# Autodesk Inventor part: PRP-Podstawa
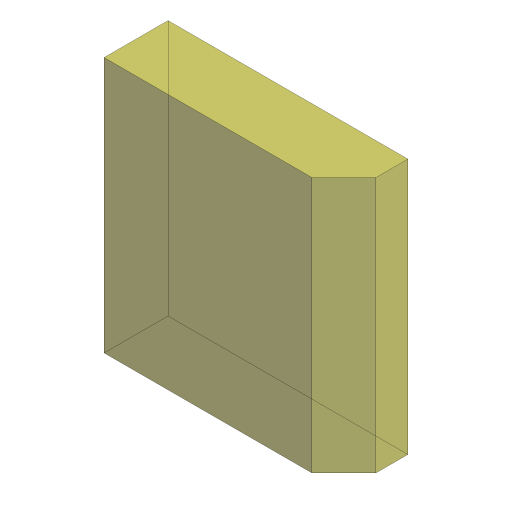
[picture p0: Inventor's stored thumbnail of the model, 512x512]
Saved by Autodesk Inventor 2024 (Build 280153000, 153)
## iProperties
Created: 2023-03
Part Number: PRP-Podstawa
Document SubType Name: Modeling
Designer: Andrzej Jaskulski
Material: Kurs-AJ
Density: 1 g/cm^3
Mass: 116 g
Surface Area: 176.314 cm^2
Volume: 116 cm^3
Appearance: Przezroczyste — żółte
Checked By: A.J.
Engr Approved By: Andrzej Jaskulski
Mfg Approved By: Andrzej Jaskulski
Authority: A.J.
Company: ATC
Control State: 0
Master: False
Checked Out: False
Shininess: 20.0
Length Units: 11269
Angle Units: 11279
Time Units: 11290
Mass Units: 11283
Length Display Precision: 3
Angle Display Precision: 2
Compacted: True
Density: 0.0
Volumn: 0.0
Area: 0.0
PropertySet Name: Model Information
Title: A.J.: Kurs R2024-MEP
Author: Andrzej Jaskulski
Revision Number: 1/24
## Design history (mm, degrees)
node "Wyciągnięcie" dims "d4" = 20, "d5" = 0
node "Fazowanie1" dims "d6" = 10, "d7" = 10, "d42" = 45 deg
node "Bryła1"
node "Korpusy bryłowe"
node "Korpusy powierzchniowe"
sketch "Sketch1"
  geometry: L1 (-25, 55)-(-25, -25); L2 (50, 55)-(-25, 55); L3 (50, -25)-(50, 55); L4 (-25, -25)-(50, -25)
  constraints: 8 end point, 2 horizontal, 2 vertical, 1 other
  dimensions: "d1" = 80 distance of L3.start L2.start; "d3" = 75 distance of L2.start L1.start
other parameters: "d2" = 75 (derived), "d8" = 0, "d12" = 6.5 (derived), "d14" = 8.5 (derived), "d29" = 46 (derived), "d31" = 43 (derived), "d33" = 21.5 (derived), "d35" = 23 (derived), "d37" = 7.679 (derived)
